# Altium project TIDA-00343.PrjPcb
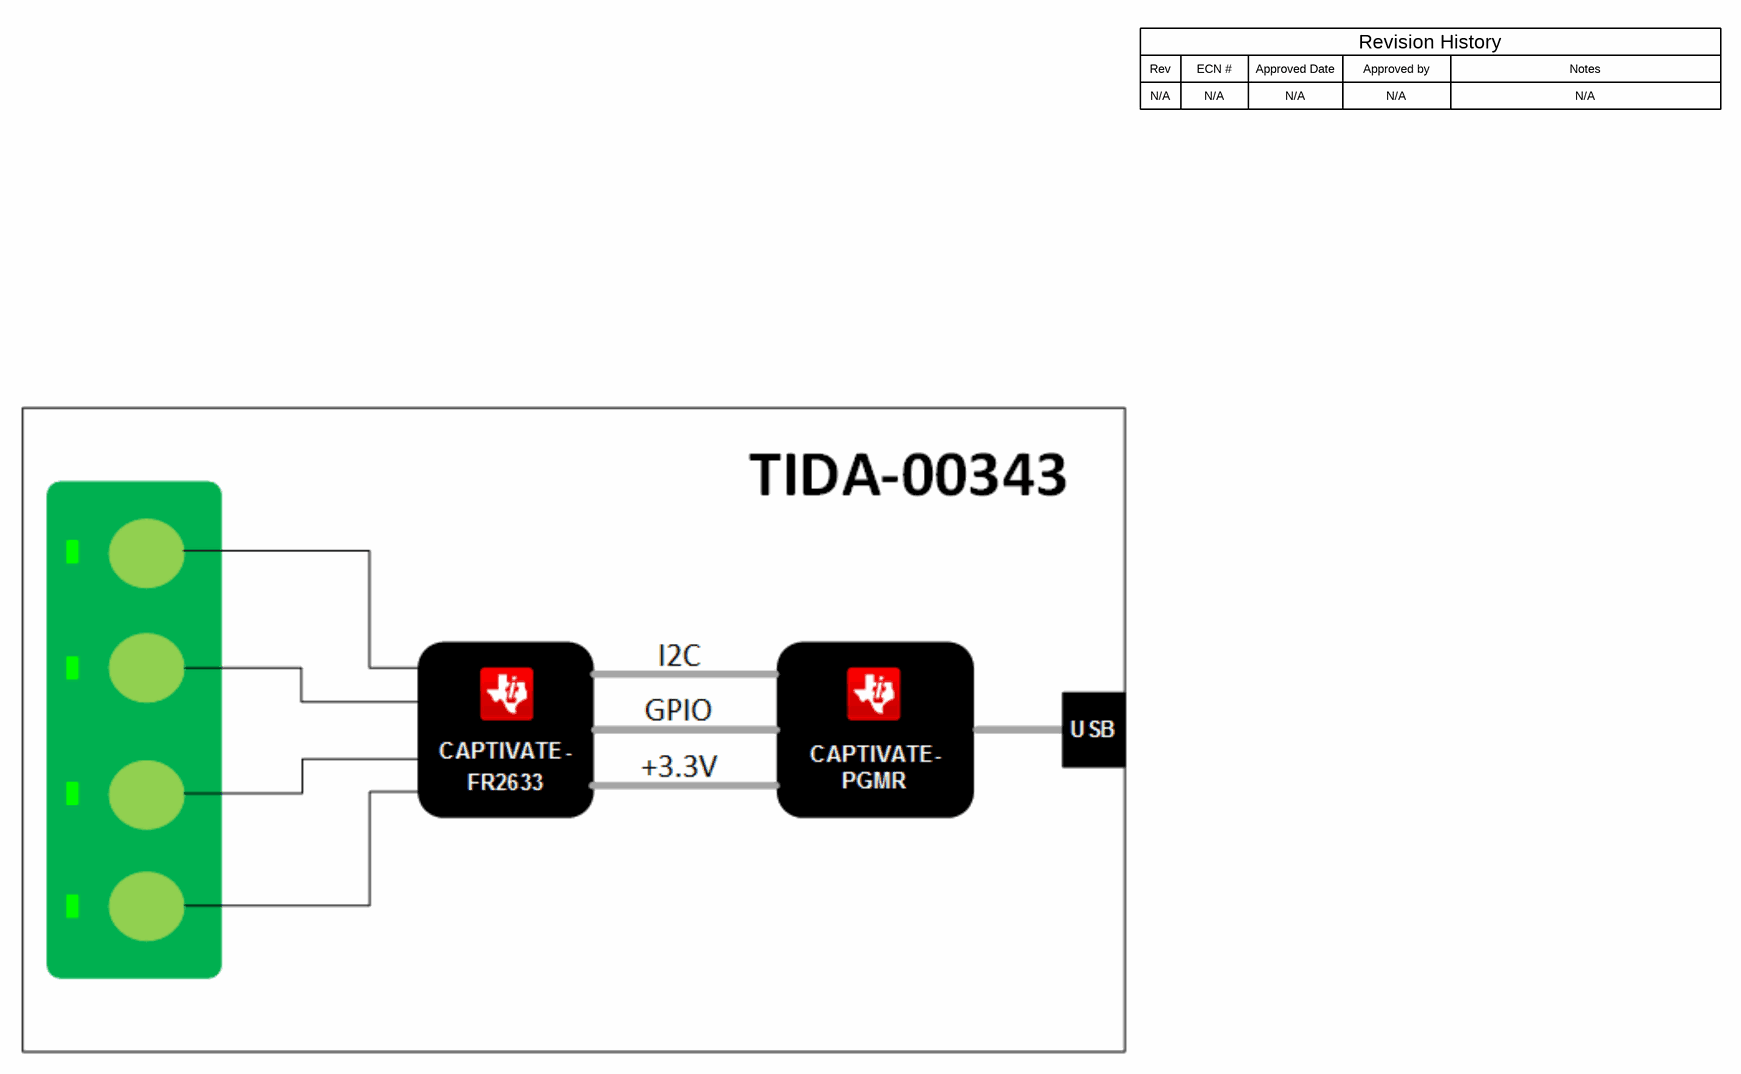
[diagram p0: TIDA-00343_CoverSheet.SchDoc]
CopyrightYear: 2016; PCB_Layout: Giovanni Campanella; PCB_Rev: E1; PRJ_Customer: Public Release; PRJ_Engineer: Giovanni Campanella; PRJ_Number: TIDA-00343; PRJ_Title: Low Power Touch Through Glass; SCH_Rev: E1; TechSupport: http://www.ti.com/support; TID: TIDA-00343
3 sheets, 24 parts. Net scope: global (net labels, ports and power ports of the same name join across sheets).
Board file: TIDA-00343.PcbDoc
Sheets:
  TIDA-00343_CoverSheet.SchDoc
  TIDA-00343_Schematic.SchDoc
  TIDA-00343_Hardware.SchDoc

## Sheet TIDA-00343_CoverSheet.SchDoc: Block Diagram TIDA-00343
size 431 x 279 mm; Date: Not shown in title block; ApprovedBy: Not shown in title block; CheckedBy: Not shown in title block; Author: Not shown in title block; CompanyName: Not shown in title block; Engineer: Not shown in title block; Organization: Not shown in title block; Address1: Not shown in title block; Address2: Not shown in title block; Address3: Not shown in title block; Address4: Not shown in title block; DocumentNumber: 1; Revision: Use project parameter SCH_Rev; SheetNumber: 1; SheetTotal: 3; PageSetup: Record=PageOptions¦CenterHorizontal=True¦CenterVertical=True¦PrintScale=1.00¦XCorrection=1.00¦YCorrection=1.00¦PrintKind=0¦BorderSize=5000000¦LeftOffset=0¦BottomOffset=0¦Orientation=2¦PaperLength=1000¦PaperWidth=1000¦Scale=100¦PaperSource=15¦PrintQuality=600¦MediaType=1¦DitherType=10¦PaperKind=Letter¦PrintScaleMode=1

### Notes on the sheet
- Rev
- N/A
- ECN #
- Approved Date
- Approved by
- Revision History
- Notes

## Sheet TIDA-00343_Schematic.SchDoc: Schematic Electodes Board
size 431 x 279 mm; Date: Not shown in title block; ApprovedBy: Not shown in title block; CheckedBy: Not shown in title block; Author: Not shown in title block; CompanyName: Not shown in title block; DrawnBy: Giovanni Campanella; Engineer: Not shown in title block; Organization: Not shown in title block; Address1: Not shown in title block; Address2: Not shown in title block; Address3: Not shown in title block; Address4: Not shown in title block; DocumentNumber: 1; Revision: Use project parameter SCH_Rev; SheetNumber: 2; SheetTotal: 3; PageSetup: Record=PageOptions¦CenterHorizontal=True¦CenterVertical=True¦PrintScale=1.00¦XCorrection=1.00¦YCorrection=1.00¦PrintKind=0¦BorderSize=5000000¦LeftOffset=0¦BottomOffset=0¦Orientation=2¦PaperLength=1000¦PaperWidth=1000¦Scale=100¦PaperSource=15¦PrintQuality=600¦MediaType=1¦DitherType=10¦PaperKind=Letter¦PrintScaleMode=1
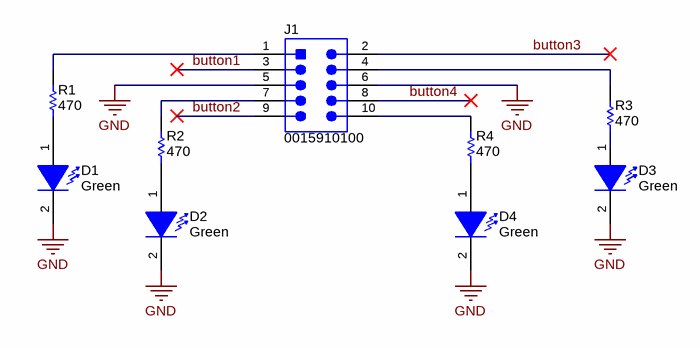
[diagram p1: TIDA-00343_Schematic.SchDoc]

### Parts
D1  value Green  [LG L29K_GREEN]  (hidden comment: LG L29K-G2J1-24-Z)
D2  value Green  [LG L29K_GREEN]  (hidden comment: LG L29K-G2J1-24-Z)
D3  value Green  [LG L29K_GREEN]  (hidden comment: LG L29K-G2J1-24-Z)
D4  value Green  [LG L29K_GREEN]  (hidden comment: LG L29K-G2J1-24-Z)
J1  0015910100  [Molex_0015910100]
R1  ValueDisplayed: 470  [0402]  (hidden comment: CRCW0402470RJNED)
R2  ValueDisplayed: 470  [0402]  (hidden comment: CRCW0402470RJNED)
R3  ValueDisplayed: 470  [0402]  (hidden comment: CRCW0402470RJNED)
R4  ValueDisplayed: 470  [0402]  (hidden comment: CRCW0402470RJNED)

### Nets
GND: D1.2(K) D2.2(K) D3.2(K) D4.2(K) J1.5 J1.6
button1: J1.3
button2: J1.9
button3: J1.2
button4: J1.8
NetD1_1: D1.1(A) R1.1
NetD2_1: D2.1(A) R2.1
NetD3_1: D3.1(A) R3.1
NetD4_1: D4.1(A) R4.1
NetJ1_1: J1.1 R1.2
NetJ1_4: J1.4 R3.2
NetJ1_7: J1.7 R2.2
NetJ1_10: J1.10 R4.2

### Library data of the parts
D1-D4 = LG L29K-G2J1-24-Z: LED, Green, SMD; Manufacturer: OSRAM; Vf_V: 1.7; Value2: 1.7V; Io_A: 0.002; Tjmax_C: 110; Value1: W; U/M: EA
J1 = 0015910100: Header, 100mil, 5x2, SMT; Manufacturer: Molex; SymbolCreator: a0412235
R1-R4 = CRCW0402470RJNED: RES, 470, 5%, 0.063 W, 0402; Manufacturer: Vishay-Dale; CompType: Resistor; Value: 470; Value_Code: 470R; Tolerance_%: 5; Power_W: 0.063; Value2: 0.063W; VDC_V: 50; TempCo: 200 ppm/C; EIA_Code: E24; U/M: EA; AEC Category: Q200

## Sheet TIDA-00343_Hardware.SchDoc: HW Electrodes Board
size 431 x 279 mm; Date: Not shown in title block; ApprovedBy: Not shown in title block; CheckedBy: Not shown in title block; Author: Not shown in title block; CompanyName: Not shown in title block; Engineer: Not shown in title block; Organization: Not shown in title block; Address1: Not shown in title block; Address2: Not shown in title block; Address3: Not shown in title block; Address4: Not shown in title block; DocumentNumber: 1; Revision: Use project parameter SCH_Rev; SheetNumber: 3; SheetTotal: 3; PageSetup: Record=PageOptions¦CenterHorizontal=True¦CenterVertical=True¦PrintScale=1.00¦XCorrection=1.00¦YCorrection=1.00¦PrintKind=0¦BorderSize=5000000¦LeftOffset=0¦BottomOffset=0¦Orientation=2¦PaperLength=1000¦PaperWidth=1000¦Scale=100¦PaperSource=15¦PrintQuality=600¦MediaType=1¦DitherType=10¦PaperKind=Letter¦PrintScaleMode=1
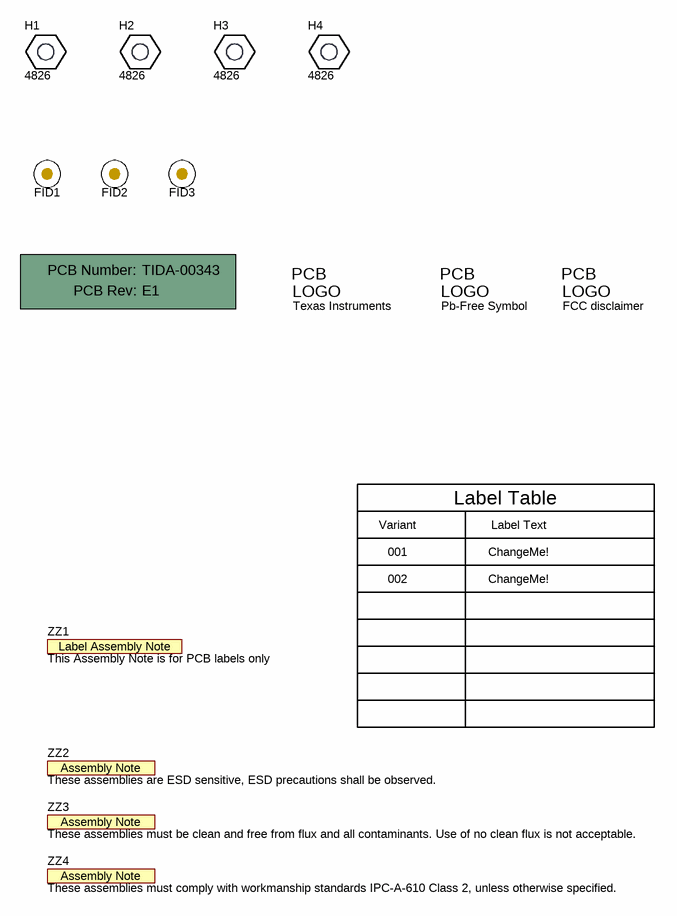
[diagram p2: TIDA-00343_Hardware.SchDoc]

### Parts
!PCB  Printed Circuit Board  (value not drawn)  (mechanical)
FID1  Fiducial  [Fiducial10-20]  (value not drawn)
FID2  Fiducial  [Fiducial10-20]  (value not drawn)
FID3  Fiducial  [Fiducial10-20]  (value not drawn)
H1  4826  [KEYSTONE_4826]
H2  4826  [KEYSTONE_4826]
H3  4826  [KEYSTONE_4826]
H4  4826  [KEYSTONE_4826]
Logo1  Texas Instruments  [TI_Stacked_Overlay_Small]  (no BOM)
Logo2  Pb-Free Symbol  [Pb-Free_Overlay_Small]  (no BOM)
Logo3  FCC disclaimer  [FCC_disclaimer]  (no BOM)
ZZ1  This Assembly Note is for PCB labels only  [AssemblyNoteLabel]  (no BOM)
ZZ2  These assemblies are ESD sensitive, ESD precautions shall be observed.  [AssemblyNote]  (no BOM)
ZZ3  These assemblies must be clean and free from flux and all contaminants. Use of no clean flux is not acceptable.  [AssemblyNote]  (no BOM)
ZZ4  These assemblies must comply with workmanship standards IPC-A-610 Class 2, unless otherwise specified.  [AssemblyNote]  (no BOM)

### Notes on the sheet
- Variant
- Label Table
- Label Text
- 001
- 002
- ChangeMe!

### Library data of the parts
!PCB = PCB: Manufacturer: Any; PartNumber: TIDA-00343; SymbolCreator: a0412235
FID1-FID3 = Fiducial: Fiducial mark.  There is nothing to buy or mount.; SymbolCreator: codlsc
H1-H4 = 4826: HEX STANDOFF 6-32 NYLON 1-3/4"; Manufacturer: Keystone; SymbolCreator: a0412235
Logo1 = TI_Logo: Texas Instrument Corporate Signature; SymbolCreator: codlsc
Logo2 = Pb-Free: SymbolCreator: a0412235
Logo3 = FCC_disclaimer: SymbolCreator: codlsc
ZZ1 = AssemblyNoteLabel: SymbolCreator: a0412235
ZZ2-ZZ4 = AssemblyNote: SymbolCreator: codlsc

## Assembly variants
001: not fitted FID1 FID2 FID3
